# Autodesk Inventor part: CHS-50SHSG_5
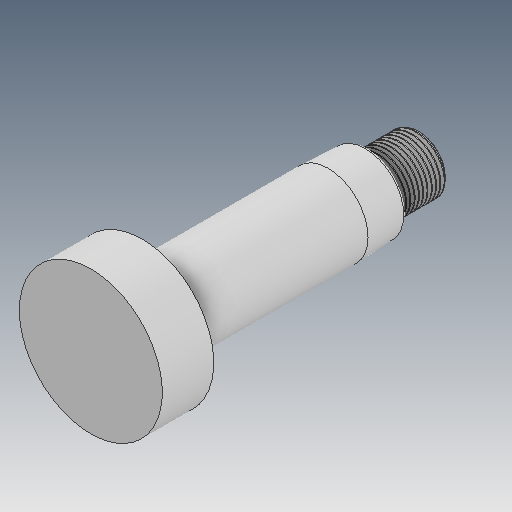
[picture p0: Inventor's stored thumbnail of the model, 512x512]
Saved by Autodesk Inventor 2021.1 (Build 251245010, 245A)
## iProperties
Created: 2019-04
Part Number: CHS-50SHSG_5
Material: Ogólny
Document SubType Name: Modeling
Designer: user
Density: 1 g/cm^3
Appearance: Domyślna
Author: user
Revision Number: ÈÎºÎ
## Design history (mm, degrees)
feature "ÊäÈë1"
node "Bryła1"
